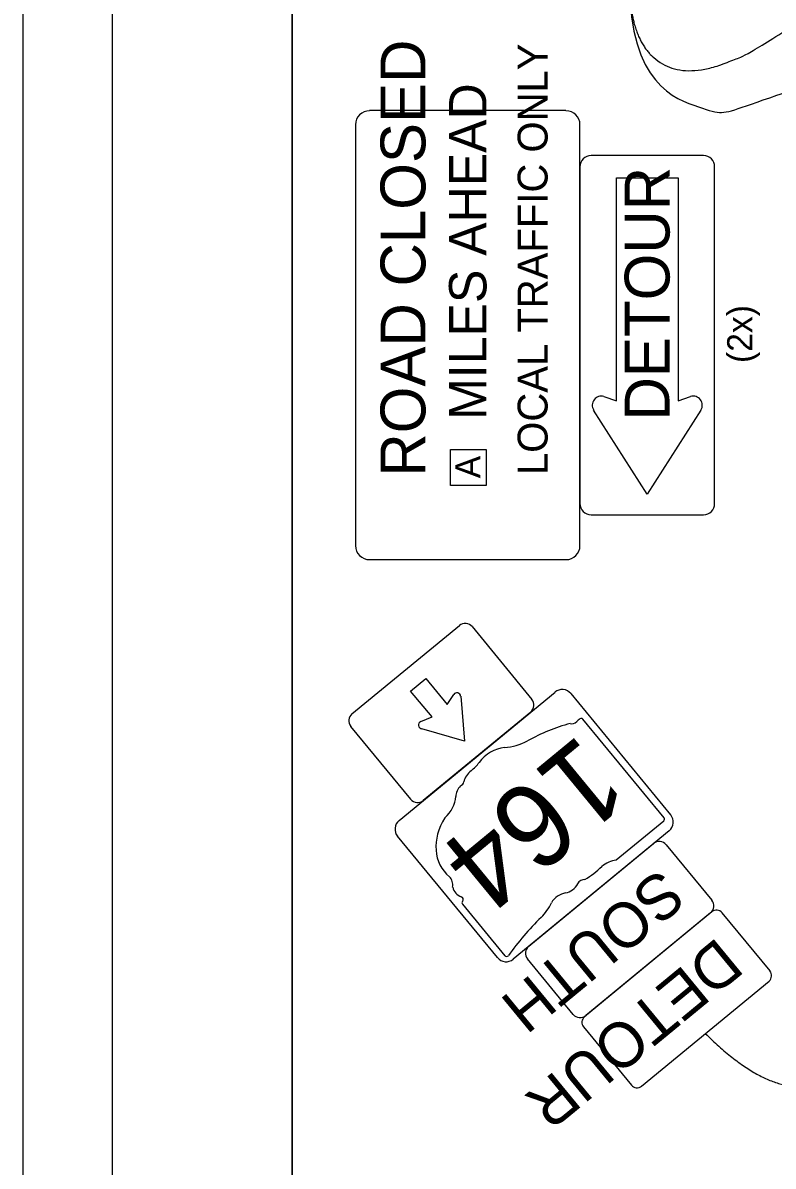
# Model space of a CAD drawing. Extents: x 0 to 1214, y 0 to 883.
# Drawn here: x 0 to 83.6, y 221.7 to 349 of the extents above; entities that cross this region are included whole.
import ezdxf

# ---------------------------------------------------------------- set-up
doc = ezdxf.new("R2010")
doc.units = 0
for name, color, linetype in [('Default', 7, 'Continuous'), ('GM_X_Minor_Lake', 7, 'Continuous'), ('GM_X_Minor_River', 7, 'Continuous'), ('GM_X_Section', 7, 'Continuous'), ('SH_Border', 7, 'Continuous'), ('SH_Cut_Line', 7, 'Continuous'), ('SH_Data', 7, 'Continuous')]:
    doc.layers.add(name, color=color, linetype=linetype)

msp = doc.modelspace()

# ---------------------------------------------------------------- linework, layer by layer
at = {"layer": 'GM_X_Minor_Lake'}
for points in [[(60.5, 339.19), (38.62, 339.19)], [(37.06, 337.62), (37.06, 290.75)], [(62.06, 290.75), (62.06, 337.62)], [(38.62, 289.19), (60.5, 289.19)]]:
    msp.add_lwpolyline(points, dxfattribs=at)
for centre, start, end in [((38.62, 337.62), 90, 180), ((60.5, 337.62), 0, 90), ((38.62, 290.75), 180, 270), ((60.5, 290.75), 270, 0)]:
    msp.add_arc(centre, 1.56, start, end, dxfattribs=at)
at = {"layer": 'GM_X_Minor_River'}
for p, q in [((66.12, 306.89), (66.12, 331.69)), ((66.12, 331.69), (73, 331.69)), ((73, 331.69), (73, 306.89)), ((64.73, 307.34), (66.12, 306.89)), ((73, 306.89), (74.38, 307.34)), ((69.56, 296.48), (63.58, 305.85)), ((75.53, 305.85), (69.56, 296.48)), ((36.66, 272.02), (48.63, 281.87)), ((50.04, 281.74), (56.71, 273.63)), ((43.19, 274.56), (44.88, 275.95)), ((44.88, 275.95), (47.27, 273.06)), ((45.58, 271.67), (43.19, 274.56)), ((47.27, 273.06), (48, 274.18)), ((48.77, 273.99), (49.2, 268.99)), ((44.33, 271.16), (45.58, 271.67)), ((56.58, 272.22), (44.61, 262.37)), ((71.42, 260.44), (62.37, 271.43)), ((43.2, 262.51), (36.53, 270.61)), ((49.2, 268.99), (44.45, 270.36)), ((66.1, 255.75), (71.4, 260.11)), ((56.36, 246.14), (70.25, 257.58)), ((71.66, 257.44), (76.75, 251.27)), ((48.97, 250.83), (53.7, 245.08)), ((48.98, 250.83), (48.97, 250.83)), ((76.61, 249.86), (62.72, 238.42)), ((61.31, 238.55), (56.22, 244.73))]:
    msp.add_line(p, q, dxfattribs=at)
for points in [[(75.81, 334.19), (63.31, 334.19)], [(62.06, 332.94), (62.06, 295.44)], [(77.06, 295.44), (77.06, 332.94)], [(63.31, 294.19), (75.81, 294.19)], [(41.91, 260.15), (59.28, 274.45)], [(61.04, 274.28), (72.16, 260.77)], [(71.99, 259.01), (54.62, 244.71)], [(52.86, 244.88), (41.74, 258.39)], [(76.76, 249.99), (62.56, 238.29)], [(83.23, 243.39), (77.89, 249.88)], [(68.92, 230.57), (83.12, 242.27)], [(62.45, 237.16), (67.79, 230.68)]]:
    msp.add_lwpolyline(points, dxfattribs=at)
for centre, radius, start, end in [((63.31, 332.94), 1.25, 90, 180), ((75.81, 332.94), 1.25, 0, 90), ((64.43, 306.39), 1, 72.1811, 212.5109), ((74.69, 306.39), 1, 327.4891, 107.8189), ((63.31, 295.44), 1.25, 180, 270), ((75.81, 295.44), 1.25, 270, 0), ((49.27, 281.1), 1, 39.4693, 129.4693), ((48.35, 273.95), 0.417, 4.8805, 146.6739), ((60.07, 273.48), 1.25, 39.4693, 129.4693), ((55.94, 273), 1, 309.4693, 39.4693), ((37.3, 271.25), 1, 129.4693, 219.4693), ((44.49, 270.77), 0.417, 112.2647, 264.4789), ((43.97, 263.14), 1, 219.4693, 309.4693), ((42.7, 259.18), 1.25, 129.4693, 219.4693), ((71.2, 259.97), 1.25, 309.4693, 39.4693), ((70.89, 256.81), 1, 39.4693, 129.4693), ((75.97, 250.63), 1, 309.4693, 39.4693), ((77.27, 249.37), 0.8, 39.4693, 129.4693), ((56.99, 245.37), 1, 129.4693, 219.4693), ((53.83, 245.67), 1.25, 219.4693, 309.4693), ((82.61, 242.88), 0.8, 309.4693, 39.4693), ((62.08, 239.19), 1, 219.4693, 309.4693), ((63.07, 237.67), 0.8, 129.4693, 219.4693), ((68.41, 231.19), 0.8, 219.4693, 309.4693)]:
    msp.add_arc(centre, radius, start, end, dxfattribs=at)
for centre, major_axis, start_param, end_param in [((63.04, 270.13), (-1.61, -1.33), 4.665946, 4.897461), ((62.14, 271.28), (-0.211, -0.174), 3.00124, 4.508301), ((62.06, 255.67), (-13.86, -11.41), 4.195997, 4.488961), ((61.28, 271.59), (-0.582, -0.479), 0.519207, 1.627899), ((54.52, 273.25), (-4.34, -3.57), 0.823519, 1.323587), ((53.33, 265.14), (-2.75, -2.27), 4.026481, 4.996735), ((48.61, 267.63), (-2.26, -1.86), 1.495662, 1.94098), ((50.86, 264.49), (-1.47, -1.21), 4.691044, 5.507374), ((50.08, 263.09), (-1.55, -1.28), 4.937069, 5.64225), ((48.66, 264.46), (-0.413, -0.34), 1.147584, 2.315152), ((45.09, 262.37), (-2.63, -2.16), 1.647645, 2.488434), ((51.76, 258.39), (-4.8, -3.95), 5.101752, 6.440018), ((71.23, 260.25), (-0.21, -0.173), 1.712693, 3.28349), ((59.08, 260.32), (-7.3, -6.01), 1.404758, 1.657858), ((65.88, 253.43), (-2.03, -1.67), 4.042523, 4.731795), ((46.27, 252.64), (-1.36, -1.12), 2.387724, 3.262537), ((62.41, 252.9), (-0.587, -0.483), 3.836095, 5.185415), ((50.06, 253.65), (-1.87, -1.54), 5.934695, 6.695948), ((60.37, 250.42), (-1.47, -1.21), 4.081561, 5.145723), ((60.51, 253.46), (-1.22, -1), 0.950623, 2.079405), ((48.67, 251.29), (-0.312, -0.257), 1.883978, 3.671073), ((49.17, 251.03), (-0.216, -0.177), 5.05454, 6.418171), ((54.72, 252), (-3.86, -3.18), 1.699011, 2.107814), ((72.26, 235.69), (-19.19, -15.8), 4.814394, 5.042369), ((53.93, 245.23), (-0.201, -0.166), 6.141152, 7.989035)]:
    msp.add_ellipse(centre, major_axis=major_axis, ratio=0.8, start_param=start_param, end_param=end_param, dxfattribs=at)
at = {"layer": 'GM_X_Section'}
msp.add_lwpolyline([(47.62, 297.45), (47.62, 301.45), (51.62, 301.45), (51.62, 297.45)], close=True, dxfattribs=at)
at = {"layer": 'SH_Border'}
for points in [[(10, 430), (30, 430), (30, 10), (10, 10)], [(30, 430), (670, 430), (670, 10), (30, 10)]]:
    msp.add_lwpolyline(points, close=True, dxfattribs=at)
at = {"layer": 'SH_Cut_Line'}
msp.add_lwpolyline([(0, 0), (680, 0), (680, 440), (0, 440)], close=True, dxfattribs=at)
at = {"layer": 'SH_Data'}
for points, degree in [([(67.58, 353.44), (67.58, 345.59), (76.87, 342.33), (95.84, 355.67), (148.43, 361.31), (164.28, 342.48), (185.84, 344.48), (186.92, 340.63)], 2), ([(67.58, 353.44), (67.58, 342.16), (77.81, 338.76), (77.81, 338.76), (94.68, 344.6), (112.52, 348.98), (137.16, 352.06), (154.68, 344.76), (174.38, 338.08), (180.94, 336.28), (186.91, 337.01), (186.92, 335.92)], 3), ([(76.02, 236.42), (89.73, 222.86), (101.11, 258.18), (149, 270.58), (187.94, 314.1), (190.55, 321.66)], 2)]:
    msp.add_open_spline(points, degree=degree, dxfattribs=at)

# ---------------------------------------------------------------- texts
at = {"layer": 'Default'}
msp.add_text('(2x)', height=2.8, rotation=90, dxfattribs=at).set_placement((81.26, 311.09))
at = {"layer": 'GM_X_Minor_Lake'}
for s, height, p in [('ROAD CLOSED', 5, (44.84, 298.43)), ('LOCAL TRAFFIC ONLY', 3.3333, (58.45, 298.61)), ('MILES AHEAD', 4.1667, (51.64, 304.76))]:
    msp.add_text(s, height=height, rotation=90, dxfattribs=at).set_placement(p)
at = {"layer": 'GM_X_Minor_River'}
for s, height, rotation, p in [('DETOUR', 5, 90, (72.04, 304.69)), ('164', 9.375, 219.4693, (62.12, 269.93)), ('SOUTH', 5, 219.4693, (71, 254.96)), ('DETOUR', 5, 219.4693, (77.4, 247.27))]:
    msp.add_text(s, height=height, rotation=rotation, dxfattribs=at).set_placement(p)
at = {"layer": 'GM_X_Section'}
msp.add_text('A', height=2.8, rotation=90, dxfattribs=at).set_placement((50.96, 298.25))

doc.saveas('drawing.dxf')
